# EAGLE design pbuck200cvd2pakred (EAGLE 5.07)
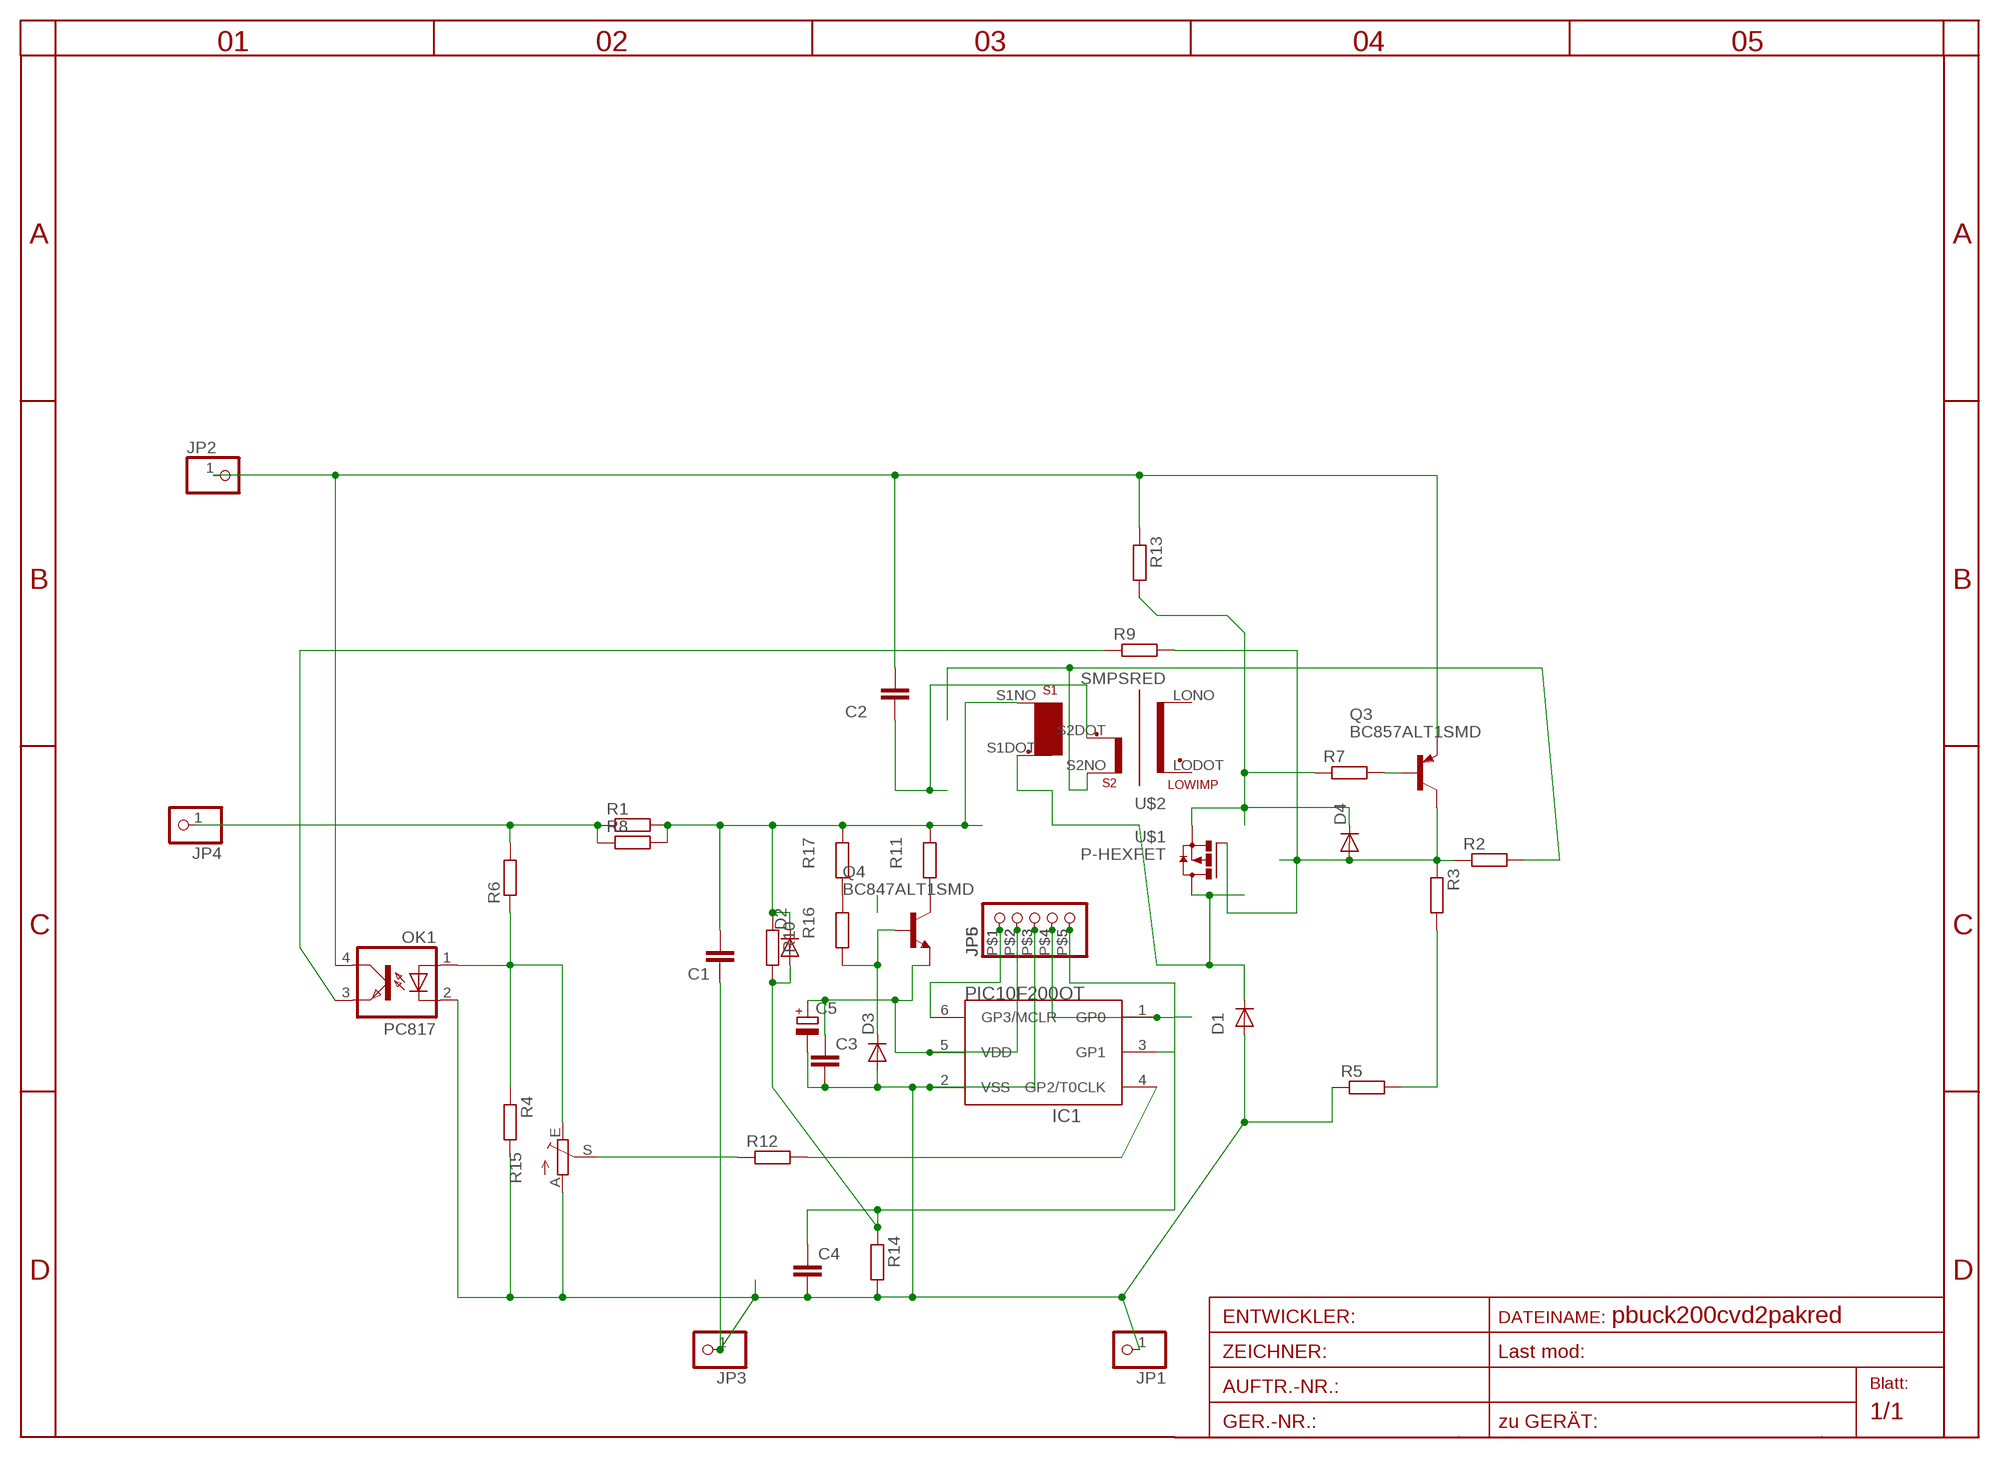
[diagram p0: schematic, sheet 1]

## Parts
C1  C-EU025-025X050  [C025-025X050]
C2  C-EUC0805  [C0805]
C3  C-EUC0805  [C0805]
C4  C-EUC0805  [C0805]
C5  CPOL-EUSMCA  [SMC_A]
D1  DIODE-SMC  [SMC]
D2  DIODE-MINIMELF  [MINIMELF]
D3  DIODE-MINIMELF  [MINIMELF]
D4  DIODE-MINIMELF  [MINIMELF]
IC1  PIC10F200OT  [SOT23-6]
JP1  PINHD-1X11MM6  [1X1MM8]
JP2  PINHD-1X11MM6  [1X1MM8]
JP3  PINHD-1X11MM6  [1X1MM8]
JP4  PINHD-1X11MM6  [1X1MM8]
JP5  PINHD-1X5  [1X05SMD]
JP6  PINHD-1X5/90  [1X05/90]
OK1  PC817  [DIL04]
Q3  BC857ALT1SMD  [SOT23-BEC]
Q4  BC847ALT1SMD  [SOT23]
R1  R-EU_R2010  [R2010]
R2  R-EU_R0805  [R0805]
R3  R-EU_R1206  [R1206]
R4  R-EU_R0805  [R0805]
R5  R-EU_R1206  [R1206]
R6  R-EU_R0805  [R0805]
R7  R-EU_R1206  [R1206]
R8  R-EU_R2512  [R2512]
R9  R-EU_R0805  [R0805]
R10  R-EU_R0805  [R0805]
R11  R-EU_R1206  [R1206]
R12  R-EU_R0805  [R0805]
R13  R-EU_R1206  [R1206]
R14  R-EU_R0805  [R0805]
R15  TRIM_EU-CA6V  [CA6V]
R16  R-EU_R1206  [R1206]
R17  R-EU_R1206  [R1206]
U$1  P-HEXFET  [D2PACK]
U$2  SMPSRED  [SMPS_R]

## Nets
-: C1.1 C3.2 C4.2 C5.- D1.A D3.A IC1.2(VSS) JP1.1 JP3.1 JP5.P$3 JP6.3 OK1.2(C) R4.2 R5.1 R14.2 R15.A
B1C2: OK1.3(EMIT) R9.1
C1: D1.C U$1.2(D) U$2.S1DOT
EB: D4.C R7.1 R13.2 U$1.3(S)
N$1: R3.2 R5.2
N$2: D4.A Q3.C R2.1 R3.1 R9.2 U$1.1(G)
N$3: Q3.B R7.2
N$4: R2.2 U$2.S2NO
N$5: Q4.3(C) R11.1
N$6: C2.1 U$2.S2DOT
N$7: JP4.1 R1.1 R6.2 R8.1
N$8: R12.1 R15.S
N$9: IC1.4(GP2/T0CLK) R12.2
N$10: D3.C Q4.1(B) R16.1
N$12: C4.1 D2.A IC1.1(GP0) JP5.P$4 JP6.4 R10.2 R14.1
N$13: R16.2 R17.1
N$14: OK1.1(A) R4.1 R6.1 R15.E
N$15: C3.1 C5.+ IC1.5(VDD) JP5.P$2 JP6.2 Q4.2(E)
N$16: IC1.3(GP1) JP5.P$5 JP6.5
N$17: IC1.6(GP3/MCLR) JP5.P$1 JP6.1
OUT+: C1.2 D2.C R1.2 R8.2 R10.1 R11.2 R17.2 U$2.S1NO
VPLUS: C2.2 JP2.1 OK1.4(COL) Q3.E R13.1
Unconnected: U$2.LODOT U$2.LONO

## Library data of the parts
C1-C4 = rcl:C-EU: CAPACITOR, European symbol
C5 = rcl:CPOL-EU: POLARIZED CAPACITOR, European symbol
D1-D4 = diode:DIODE-: DIODE
IC1 = microchip-5:PIC10F20*: uPC nW 0,25/0,5k Program Flash memory
JP1-JP4 = pinhead:PINHD-1X1: PIN HEADER
JP5 JP6 = pinhead:PINHD-1X5: PIN HEADER
OK1 = optocoupler:PC817: SHARP OPTO COUPLER
Q3 = transistor-pnp:BC857*: PNP Transistror
Q4 = transistor-npn:BC847*: NPN Transistor
R1-R14 R16 R17 = rcl:R-EU_: RESISTOR, European symbol
R15 = pot:TRIM_EU-: POTENTIOMETER
U$1 = transistor-power:P-HEXFET
U$2 = trafo:SMPSRED

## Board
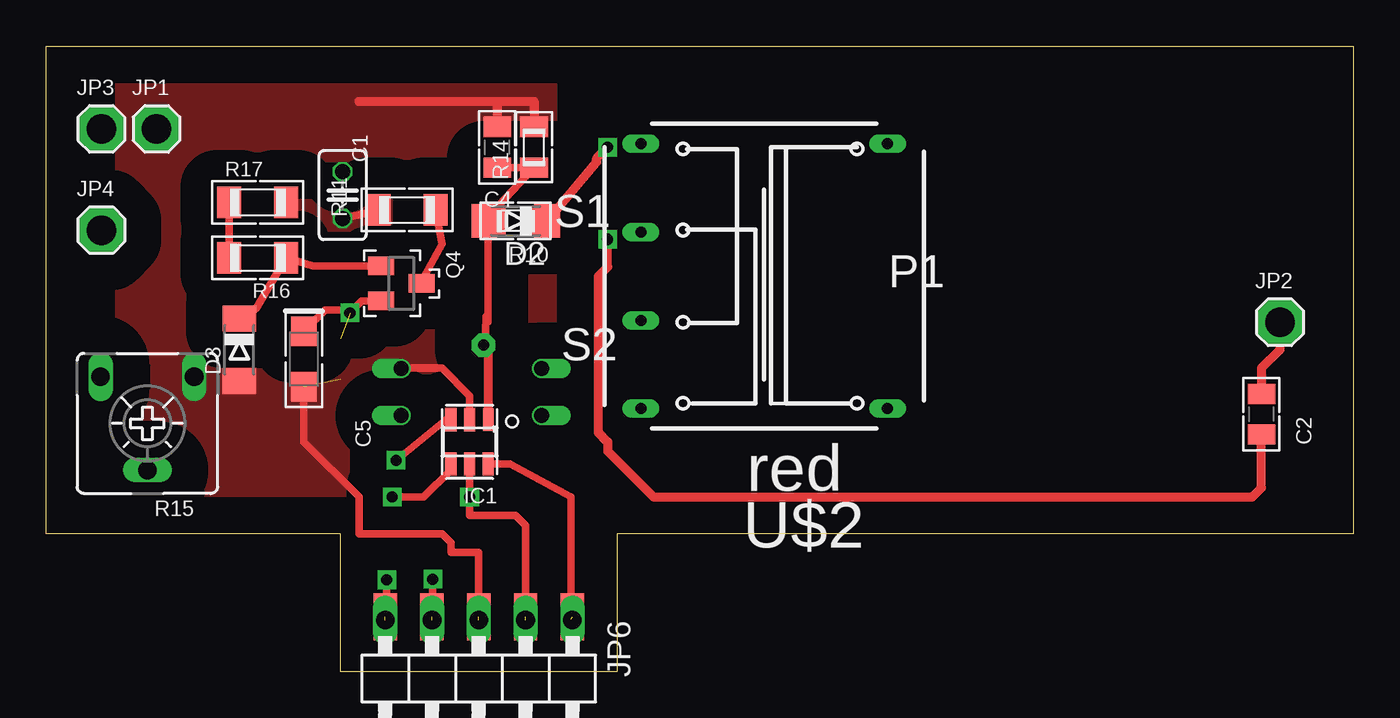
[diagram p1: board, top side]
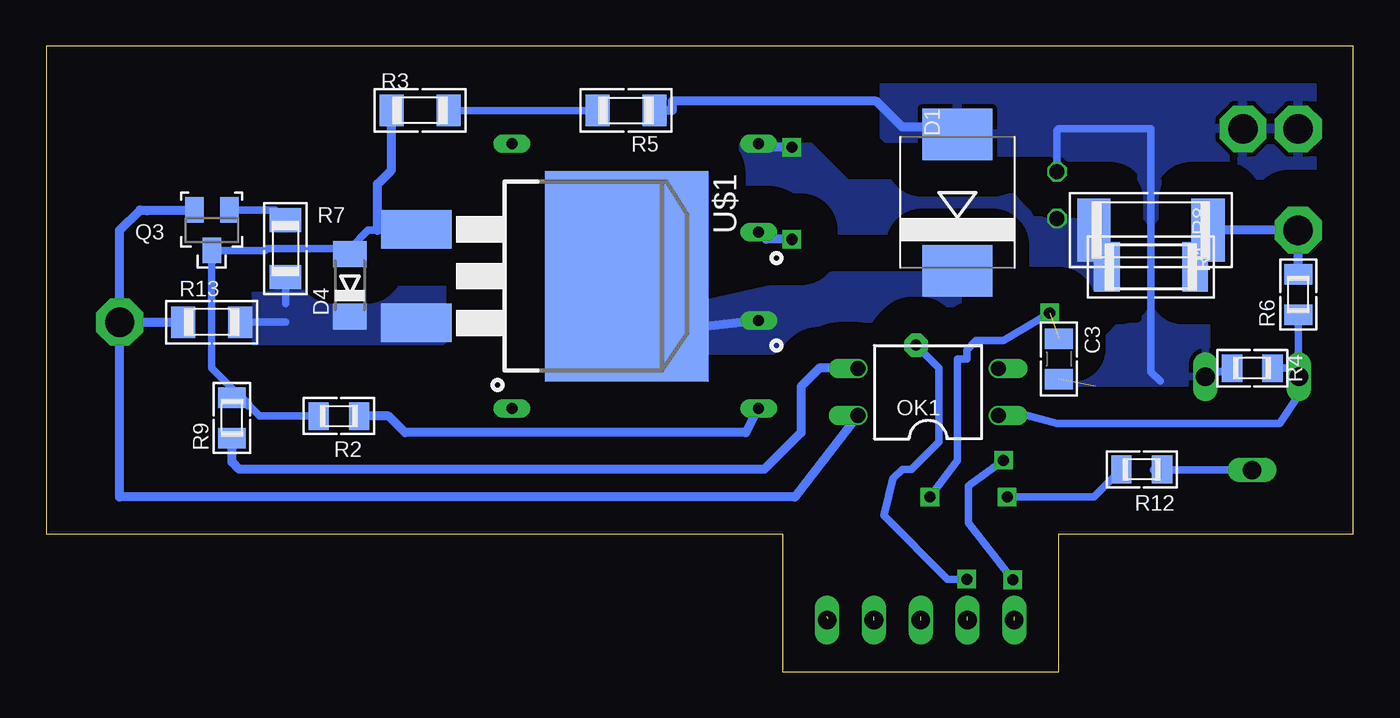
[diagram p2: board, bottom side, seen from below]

Size 71 x 34 mm. Coordinates in mm from the lower left corner, seen from the top.
Outline: 0,34 71,34 71,7.5 31,7.5 31,0 16,0 16,7.5 0,7.5 0,34
Copper layers (1*16): Top 0.035mm / dielectric 1.5mm / Bottom 0.035mm
Design rules "default *": minimum track width 10mil, minimum drill 20mil, track to track 8mil, track to pad 8mil, pad to pad 8mil, via to via 8mil, smd to smd 8mil, copper to edge 40mil, drill to drill 8mil, minimum pad ring 1mil, minimum via ring 8mil, stop-mask expansion 4mil, vias tented up to drill 0mil, thermal gap 10mil

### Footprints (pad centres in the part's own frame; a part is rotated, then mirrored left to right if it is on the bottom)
C025-025X050 = drill 0.813 octagon: 1 -1.27,0; 2 1.27,0
C0805 = smd 1.1 x 1.5: 1 -1.1,0; 2 1.1,0
SMC_A = smd 1.6 x 1.4: + -1.5,0; - 1.5,0
SMC = smd 2.8 x 3.8: A 3.7,0; C -3.7,0
MINIMELF = smd 1.4 x 1.8: A 1.7,0; C -1.7,0
SOT23-6 = smd 0.55 x 1.2: 1 -1.016,-1.2 | smd 0.6 x 1.27: 2 0,-1.2; 3 1.016,-1.2; 4 1.016,1.2; 5 0,1.2; 6 -1.016,1.2
1X1MM8 = drill 1.6 pad 2.54 octagon: 1 0,0
1X05SMD = smd 1.27 x 2.54: P$1 -5.08,0; P$2 -2.54,0; P$3 0,0; P$4 2.54,0; P$5 5.08,0
1X05/90 = drill 1.016 long: 1 -5.08,-3.81; 2 -2.54,-3.81; 3 0,-3.81; 4 2.54,-3.81; 5 5.08,-3.81
DIL04 = drill 0.813 offset: 1 -1.27,-3.81; 2 1.27,-3.81; 3 1.27,3.81; 4 -1.27,3.81
SOT23-BEC = smd 1 x 1.4: B -0.95,-1.1; C 0,1.1; E 0.95,-1.1
SOT23 = smd 1 x 1.4: 1 -0.95,-1.1; 2 0.95,-1.1; 3 0,1.1
R2010 = smd 1.4 x 2.7: 1 -2.4,0; 2 2.4,0
R0805 = smd 1.1 x 1.5: 1 -1.1,0; 2 1.1,0
R1206 = smd 1.3 x 1.7: 1 -1.55,0; 2 1.55,0
R2512 = smd 1.8 x 3.4: 1 -3.1,0; 2 3.1,0
CA6V = drill 1.016 long: A -2.54,-2.54; E 2.54,-2.54; S 0,2.54
D2PACK = smd 2.083 x 3.81: 1 -2.54,-8.89; 3 2.54,-8.89 | smd 11.43 x 8.89: 2 0,2.54
SMPS_R = drill 0.6 pad 1 long: LODOT 6.7,-7.2; LONO 6.7,7.2; S1NO -6.7,7.2 | drill 0.6 pad 1.016 long: S1DOT -6.7,-2.4; S2DOT -6.7,2.4; S2NO -6.7,-7.2

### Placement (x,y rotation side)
C1  16.1,25.9 270 top
C2  66,14 90 top
C3  16,17 270 bottom
C4  24.5,28.5 90 top
C5  14,17 270 top
D1  21.5,25.5 90 bottom
D2  25.5,24.5 180 top
D3  10.5,17.5 270 top
D4  54.5,21 90 bottom
IC1  23,12.5 180 top
JP1  6,29.5 0 top
JP2  67,19 0 top
JP3  3,29.5 0 top
JP4  3,24 0 top
JP5  23.5,3 180 top
JP6  23.5,-1 180 top
OK1  23.1,15.2 90 bottom
Q3  62,24 180 bottom
Q4  19.3,21.1 270 top
R1  11,22 180 bottom
R2  55.1,13.9 0 bottom
R3  50.69,30.5 0 bottom
R4  5.5,16.5 180 bottom
R5  39.5,30.5 180 bottom
R6  3,20.5 90 bottom
R7  58,23 90 bottom
R8  11,24 180 bottom
R9  60.9,13.8 90 bottom
R10  25.5,24.5 180 top
R11  19.6,25.1 180 top
R12  11.5,11 180 bottom
R13  62,19 0 bottom
R14  26.5,28.5 90 top
R15  5.5,13.5 180 top
R16  11.5,22.5 180 top
R17  11.5,25.5 0 top
U$1  42,21.5 270 bottom
U$2  39,21.5 0 top

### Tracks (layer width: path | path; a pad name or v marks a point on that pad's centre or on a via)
-  (2 unrouted)
  Top 0.406: IC1.2 23,15 21.5,16.5 19.32,16.5 OK1.2 | JP5.P$3 23.5,6.5 22,6.5 22,7 21.5,7.5 17,7.5 17,9.5 14,12.5 C5.-
  Top 0.5: C4.2 24.5,31 19,31 | R14.2 26.5,31 17,31
  Bottom 0.406: R4.2 8.06,16.04 R15.A | OK1.2 19.32,16.5 | C1.1 16.1,29.4 16,29.5 11,29.5 11,16.3 D3.A
  Bottom 0.5: R5.1 37,30.5 37,31 25.9,31 C4.2 21.9,29.6 D1.A
  pour Bottom (isolate 2, rank 2): 1.5,32 25.5,32 25.5,26.5 1.5,26.5
  pour Top (isolate 2, rank 3, no thermals): 4,32 27.5,32 27.5,11.5 27,8.5 4,8.5
  pour Bottom (isolate 1.778, rank 2): 18.5,15.5 8,15.5 8,19 8.5,19 10.5,21 10.5,26.5 11,27 11.5,27 12,26.5 12,19.5 14,17.5 18,17.5 18.5,17
B1C2
  Bottom 0.5: R9.1 60.9,11.4 60.5,11 32,11 30,13 30,15.5 29,16.5 26.94,16.5 OK1.3
C1
  Bottom 0.5: U$2.S1DOT 36.56,18.6 U$1.2
  pour Bottom (isolate 2, rank 2, no thermals): 21.5,23 35,20 37,17.5 21.5,17.5
EB
  Bottom 0.406: 58,20 R7.1 | 58,19 R13.2
  pour Bottom (isolate 2, rank 2, no thermals): 49.5,18 49.5,21 61.5,21 61.5,18
N$1
  Bottom 0.406: R5.2 R3.2
N$2
  Bottom 0.406: R2.1 59.4,13.9 60,14.5 62,16.5 Q3.C 59.1,22.9 59,23 54.8,23 D4.A 54.5,23 53.5,24 53,24 50.93,24 U$1.1
  Bottom 0.5: R3.1 52.24,27.26 53,26.5 53,24 | R9.2 60.4,14.9 60,14.5
N$3
  Bottom 0.406: Q3.B 58.55,25.1 R7.2
N$4
  Bottom 0.5: U$2.S2NO 32.5,14 33,13 51.5,13 52.4,13.9 R2.2
N$5
  Top 0.406: Q4.3 20.6,21.6 21.5,23.25 R11.1
N$6  (via drill 0.6)
  Top 0.5: C2.1 66,10 65.5,9.5 33,9.5 30.5,12 30.5,12.5 30,13 30,21.5 30.5,22 v30.5,23.5
  Bottom 0.5: v30.5,23.5 31.9,23.5 U$2.S2DOT
N$7
  Bottom 0.5: R6.2 JP4.1 R8.1 7.9,23.2 R1.1
N$8
  Bottom 0.406: R15.S 10.86,10.96 R12.1
N$9  (via drill 0.6)
  Top 0.406: IC1.4 21.98,10.98 20.5,9.5 v18.8,9.5
  Bottom 0.406: v18.8,9.5 14.1,9.5 R12.2
N$10
  Top 0.406: D3.C 11.4,19.75 R16.1 14.5,22.05 Q4.1
N$12  (via drill 0.6, 0.6 pad 1.27)  (1 unrouted)
  Top 0.406: JP5.P$4 v21,5.04 | C4.1 R14.1 D2.A 23.3,24.5 | 23.3,24.5 24,23.5 24,19 23.9,19.3 23.85,17.75 v23.75,17.75 | 23.3,24.5 24.2,24.3 R10.2
  Top 0.5: IC1.1 24.02,17.48 v23.75,17.75
  Bottom 0.406: v21,5.04 22.04,5.04 25.5,8.5 25,10.5 24.5,11 24,11 22.5,12.5 22.5,16.5 v23.75,17.75
N$13
  Top 0.406: R16.2 R17.1
N$14
  Bottom 0.406: OK1.1 18.02,14 16.1,13.5 4,13.5 2.96,15.04 R15.E | R6.1 3,16.08 R15.E | R4.1 3.42,16.5 R15.E
N$15  (via drill 0.6)  (2 unrouted)
  Top 0.406: JP5.P$2 26.04,7.96 25.5,8.5 23,8.5 v23,9.5 IC1.5 | C5.+ 15.15,19.65 16.35,19.65 v16.5,19.5 17.15,20.15 Q4.2
  Bottom 0.406: v16.5,19.5 19,18 20.5,18 21,17.5 21,17 21.5,17 21.5,11.5 v23,9.5
N$16  (via drill 0.6)  (1 unrouted)
  Top 0.406: IC1.3 21.7,13.7 v19,11.5 | JP6.5 18.5,2.81 v18.5,5
  Bottom 0.406: v19,11.5 20.9,10.1 20.9,8.1 v18.5,5
N$17  (1 unrouted)
  Top 0.406: IC1.6 25.2,11.3 28.5,9.5 28.5,2.89 JP6.1
OUT+  (via drill 0.6)
  Top 0.406: C1.2 R11.2 | D2.C R10.1
  Top 0.5: D2.C 29.9,27.7 29.9,27.9 v30.5,28.5
  Bottom 0.5: v30.5,28.5 32.1,28.5 U$2.S1NO
  pour Bottom (isolate 2, no thermals): 30,29 34,29 34,25.5 31,24 20.5,24 15.5,21 13.5,21 13.5,24 15.5,24.5 17.5,24.5 18.5,26.5 27.5,26.5
  pour Top (isolate 1.676, rank 2, no thermals): 13,25.5 19,25.5 19,23.5 13,23.5
VPLUS
  Top 0.5: C2.2 66,16.5 67,17.5 JP2.1
  Bottom 0.406: Q3.E 65.4,25.1 65.5,25
  Bottom 0.5: JP2.1 67,9.5 30.34,9.5 OK1.4 | Q3.E 65.9,25.1 67,24 JP2.1 | JP2.1 R13.1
